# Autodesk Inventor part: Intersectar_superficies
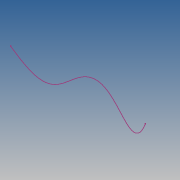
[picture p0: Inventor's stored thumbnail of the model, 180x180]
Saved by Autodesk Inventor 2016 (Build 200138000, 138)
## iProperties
Created: 2015-09
Part Number: Intersectar_superficies
Material: Generic
Document SubType Name: Modeling
Designer: julian.chica
Density: 1 g/cm^3
Appearance: Default
Author: julian.chica
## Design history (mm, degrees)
sketch "CURVA 1"
  geometry: L1 (1000, -140)-(600, -824.243); L2 (600, -824.243)-(300, 0); L3 (300, 0)-(-300, 0); L4 (-300, 0)-(-600, -824.243); L5 (-600, -824.243)-(-1000, -140); 2 further points
  constraints: 3 horizontal alignment, 1 coincident, 1 midpoint, 3 other
  dimensions: "d0" = 2000 distance of L5.end L1.start; "d1" = 1000 horizontal distance of L1.start point (0, 0); "d2" = 600 distance of L2.end L3.end; "d3" = 1200 distance of L1.end L4.end; "d4" = 110 deg angle of L3 L2; "d5" = 110 deg angle of L4 L3; "d6" = 140 vertical distance of point (0, 0) L1.start
sketch "CURVA 2"
  geometry: A1 r 2000 centre (0, -1200) between (1000, 532.051) and (-1000, 532.051); 1 further point
  constraints: 2 point on circle, 1 centre point, 1 vertical alignment
  dimensions: "d7" = 2000 distance of A1.start A1.end; "d8" = 1200 distance of point (0, 0) A1.centre; "d9" = 1000 horizontal distance of point (0, 0) A1.end; "d11" = 2000 radius of A1
extrude_surface "ExtrusionSrf1" dims "d12" = 1030.25, "d13" = 0
extrude_surface "ExtrusionSrf2" dims "d14" = 1022, "d15" = 0
sketch "3D Sketch1"
  node "3D Intersection1"
body "Srf1"
body "Srf2"
